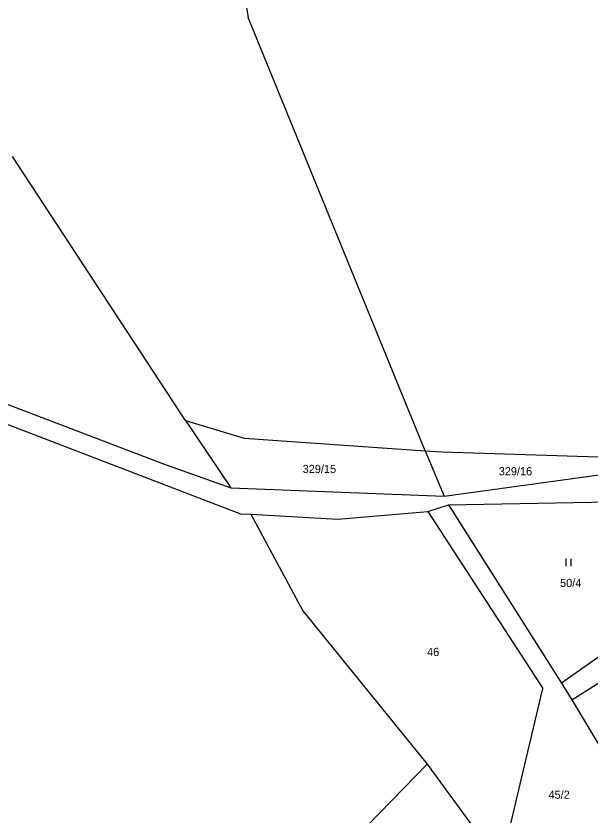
# Model space of a CAD drawing. Extents: x -633485 to -630509, y -1112692 to -1108818.
# Drawn here: x -632090.4 to -631971.2, y -1111718.1 to -1111552 of the extents above; entities that cross this region are included whole.
import ezdxf
from ezdxf.enums import TextEntityAlignment as Align

# ---------------------------------------------------------------- set-up
doc = ezdxf.new("R2010")
doc.units = 0
doc.header["$LTSCALE"] = 0.68
doc.layers.add('1', color=7, linetype='Continuous', lineweight=25)
doc.layers.add('3', color=7, linetype='Continuous', lineweight=25)
doc.layers.add('2', color=7, linetype='Continuous')

msp = doc.modelspace()

# ---------------------------------------------------------------- linework, layer by layer
at = {"layer": '1'}
for p, q in [((-632044.64, -1111536.99), (-632042.2, -1111552.26)), ((-632005.46, -1111642.22), (-632042.2, -1111552.26)), ((-632055.22, -1111635.97), (-632091.14, -1111581.12)), ((-632111.85, -1111625.08), (-632059.97, -1111644.91)), ((-632113.47, -1111628.57), (-632043.78, -1111655.3)), ((-632055.22, -1111635.97), (-632043, -1111639.62)), ((-632055.22, -1111635.97), (-632045.82, -1111649.92)), ((-632043, -1111639.62), (-632005.46, -1111642.22)), ((-632005.46, -1111642.22), (-632001.49, -1111651.65)), ((-632005.46, -1111642.22), (-632001.91, -1111642.47)), ((-632001.91, -1111642.47), (-631947.56, -1111644.22)), ((-632001.49, -1111651.65), (-631947.56, -1111644.22)), ((-632059.97, -1111644.91), (-632045.82, -1111649.92)), ((-632045.82, -1111649.92), (-632001.49, -1111651.65)), ((-632000.57, -1111653.43), (-631958.43, -1111652.69)), ((-632004.86, -1111654.83), (-632000.57, -1111653.43)), ((-632000.57, -1111653.43), (-631977.11, -1111690.5)), ((-632043.78, -1111655.3), (-632041.62, -1111655.39)), ((-632041.62, -1111655.39), (-632030.85, -1111675.49)), ((-632041.62, -1111655.39), (-632023.54, -1111656.41)), ((-632023.54, -1111656.41), (-632004.86, -1111654.83)), ((-632004.86, -1111654.83), (-631981.02, -1111691.61)), ((-632030.85, -1111675.49), (-632005.02, -1111707.28)), ((-631957.55, -1111676.64), (-631977.11, -1111690.5)), ((-631977.11, -1111690.5), (-631974.95, -1111693.92)), ((-631974.95, -1111693.92), (-631967.87, -1111689.47)), ((-631989.69, -1111728.27), (-631981.02, -1111691.61)), ((-631974.95, -1111693.92), (-631965, -1111710.64)), ((-632017.35, -1111719.93), (-632005.02, -1111707.28)), ((-632005.02, -1111707.28), (-631989.69, -1111728.27))]:
    msp.add_line(p, q, dxfattribs=at)
at = {"layer": '3'}
for p, q in [((-631976.121, -1111666.18), (-631976.121, -1111664.68)), ((-631975.12, -1111666.18), (-631975.12, -1111664.68))]:
    msp.add_line(p, q, dxfattribs=at)

# ---------------------------------------------------------------- texts
at = {"layer": '2'}
for s, p in [('329/15', (-632030.88, -1111646.855)), ('329/16', (-631990.16, -1111647.335)), ('46', (-632005.04, -1111684.845)), ('45/2', (-631979.82, -1111714.485))]:
    msp.add_text(s, height=1.7, dxfattribs=at).set_placement(p)
msp.add_text('50/4', height=1.7, dxfattribs=at).set_placement((-631975.199, -1111670.522), align=Align.CENTER)

doc.saveas('drawing.dxf')
